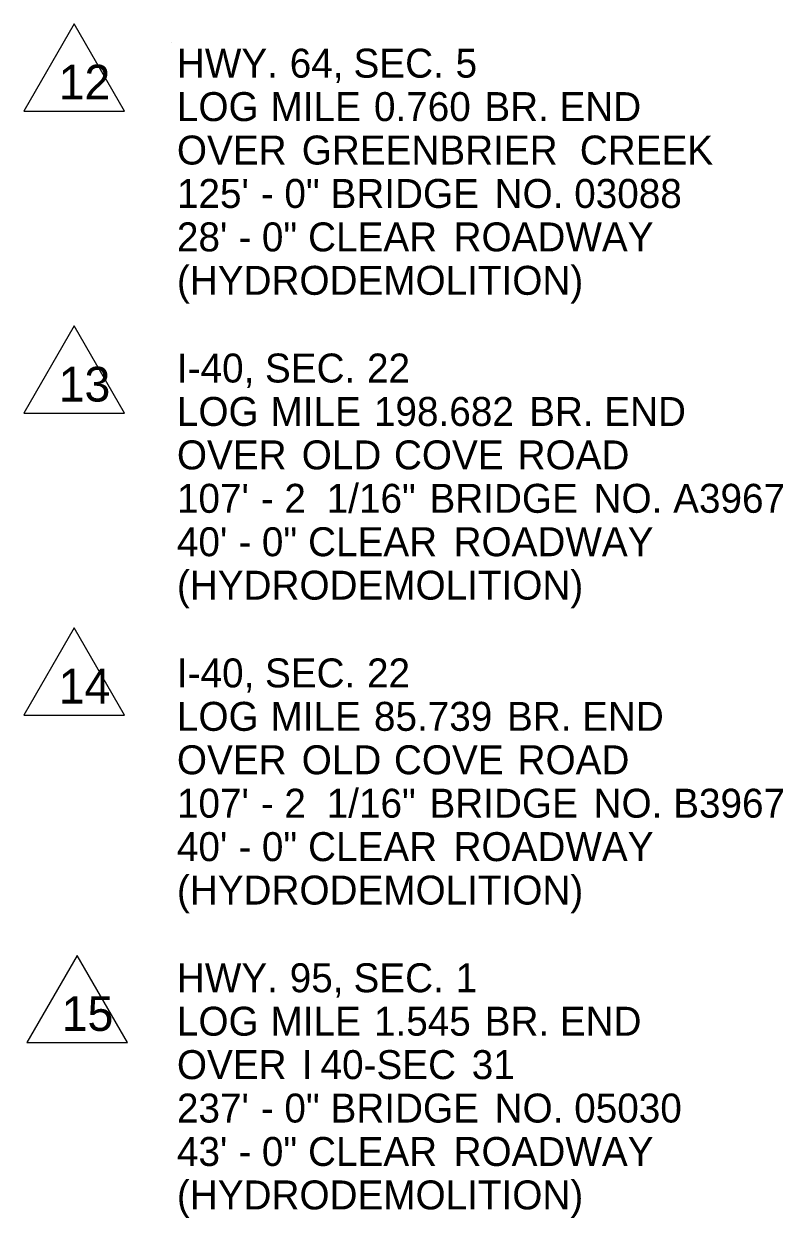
# Model space of a CAD drawing. Extents: x -17668 to 16999, y -17303 to 5867.
# Drawn here: x -17097 to -15129, y -14532 to -11438 of the extents above; entities that cross this region are included whole.
import ezdxf

# ---------------------------------------------------------------- set-up
doc = ezdxf.new("R2010")
doc.units = 0
doc.layers.add('48', color=7, linetype='Continuous')
doc.layers.add('Default', color=7, linetype='Continuous')

msp = doc.modelspace()

# ---------------------------------------------------------------- linework, layer by layer
at = {"layer": '48'}
for p, q in [((-16966, -11438.2), (-17096.6, -11664.4)), ((-16835.4, -11664.4), (-16966, -11438.2)), ((-16714.5, -11487.5), (-16714.5, -11487.5)), ((-17096.6, -11664.4), (-16835.4, -11664.4)), ((-16966, -12220.6), (-17096.6, -12446.9)), ((-16835.4, -12446.9), (-16966, -12220.6)), ((-17096.6, -12446.9), (-16835.4, -12446.9)), ((-16966, -13003.1), (-17096.6, -13229.3)), ((-16835.4, -13229.3), (-16966, -13003.1)), ((-17096.6, -13229.3), (-16835.4, -13229.3)), ((-16958.2, -13851.1), (-17088.8, -14077.3)), ((-16827.6, -14077.3), (-16958.2, -13851.1)), ((-17088.8, -14077.3), (-16827.6, -14077.3))]:
    msp.add_line(p, q, dxfattribs=at)

# ---------------------------------------------------------------- texts
for s, p in [('12', (-17006.4, -11634)), ('13', (-17006.4, -12416.5)), ('14', (-17006.4, -13198.9)), ('15', (-16998.6, -14046.9))]:
    msp.add_text(s, height=90, dxfattribs=at).set_placement(p)
at = {"layer": 'Default'}
for s, p in [('HWY.', (-16699.9, -11577.5)), (' 64,', (-16435.4, -11577.5)), (' SEC.', (-16270.1, -11577.5)), (' 5', (-16005.5, -11577.5)), ('LOG', (-16699.9, -11690)), (' MILE', (-16485.2, -11690)), (' 0.760', (-16217.1, -11690)), (' BR.', (-15931, -11690)), (' END', (-15736.3, -11690)), ('OVER', (-16699.9, -11802.5)), (' GREENBRIER', (-16404.3, -11802.5)), (' CREEK', (-15683.6, -11802.5)), ("125'", (-16699.9, -11915)), (' 0"', (-16449.3, -11915)), (' BRIDGE', (-16329.7, -11915)), (' NO.', (-15904.4, -11915)), (' 03088', (-15698.1, -11915)), (' -', (-16510, -11915)), ("28'", (-16699.9, -12027.5)), (' 0"', (-16507.6, -12027.5)), (' CLEAR', (-16387.9, -12027.5)), (' ROADWAY', (-16010.8, -12027.5)), (' -', (-16568.3, -12027.5)), ('(HYDRODEMOLITION)', (-16699.9, -12140)), ('I-40,', (-16699.9, -12367.2)), (' SEC.', (-16499.6, -12367.2)), (' 22', (-16235.1, -12367.2)), ('LOG', (-16699.9, -12479.7)), (' MILE', (-16485.2, -12479.7)), (' 198.682', (-16217.1, -12479.7)), (' BR.', (-15815, -12479.7)), (' END', (-15620.3, -12479.7)), ('OVER', (-16699.9, -12592.2)), (' OLD', (-16404.3, -12592.2)), (' COVE', (-16165.3, -12592.2)), (' ROAD', (-15844.8, -12592.2)), ("107'", (-16699.9, -12704.7)), (' 2', (-16449.3, -12704.7)), ('  1/16"', (-16367.5, -12704.7)), (' BRIDGE', (-16073.2, -12704.7)), (' NO.', (-15647.9, -12704.7)), (' A3967', (-15441.6, -12704.7)), (' -', (-16510, -12704.7)), ("40'", (-16699.9, -12817.2)), (' 0"', (-16507.6, -12817.2)), (' CLEAR', (-16387.9, -12817.2)), (' ROADWAY', (-16010.8, -12817.2)), (' -', (-16568.3, -12817.2)), ('(HYDRODEMOLITION)', (-16699.9, -12929.7)), ('I-40,', (-16699.9, -13157)), (' SEC.', (-16499.6, -13157)), (' 22', (-16235.1, -13157)), ('LOG', (-16699.9, -13269.5)), (' MILE', (-16485.2, -13269.5)), (' 85.739', (-16217.1, -13269.5)), (' BR.', (-15872.3, -13269.5)), (' END', (-15677.7, -13269.5)), ('OVER', (-16699.9, -13382)), (' OLD', (-16404.3, -13382)), (' COVE', (-16165.3, -13382)), (' ROAD', (-15844.8, -13382)), ("107'", (-16699.9, -13494.5)), (' 2', (-16449.3, -13494.5)), ('  1/16"', (-16367.5, -13494.5)), (' BRIDGE', (-16073.2, -13494.5)), (' NO.', (-15647.9, -13494.5)), (' B3967', (-15441.6, -13494.5)), (' -', (-16510, -13494.5)), ("40'", (-16699.9, -13607)), (' 0"', (-16507.6, -13607)), (' CLEAR', (-16387.9, -13607)), (' ROADWAY', (-16010.8, -13607)), (' -', (-16568.3, -13607)), ('(HYDRODEMOLITION)', (-16699.9, -13719.5)), ('HWY.', (-16699.9, -13946.7)), (' 95,', (-16435.4, -13946.7)), (' SEC.', (-16270.1, -13946.7)), (' 1', (-16005.5, -13946.7)), ('LOG', (-16699.9, -14059.2)), (' MILE', (-16485.2, -14059.2)), (' 1.545', (-16217.1, -14059.2)), (' BR.', (-15930.1, -14059.2)), (' END', (-15735.5, -14059.2)), ('OVER', (-16699.9, -14171.7)), (' I', (-16404.3, -14171.7)), (' 40-SEC', (-16355.5, -14171.7)), (' 31', (-15963.7, -14171.7)), ("237'", (-16699.9, -14284.2)), (' 0"', (-16449.3, -14284.2)), (' BRIDGE', (-16329.7, -14284.2)), (' NO.', (-15904.4, -14284.2)), (' 05030', (-15698.1, -14284.2)), (' -', (-16510, -14284.2)), ("43'", (-16699.9, -14396.7)), (' 0"', (-16507.6, -14396.7)), (' CLEAR', (-16387.9, -14396.7)), (' ROADWAY', (-16010.8, -14396.7)), (' -', (-16568.3, -14396.7)), ('(HYDRODEMOLITION)', (-16699.9, -14509.2))]:
    msp.add_text(s, height=75, dxfattribs=at).set_placement(p)

doc.saveas('drawing.dxf')
